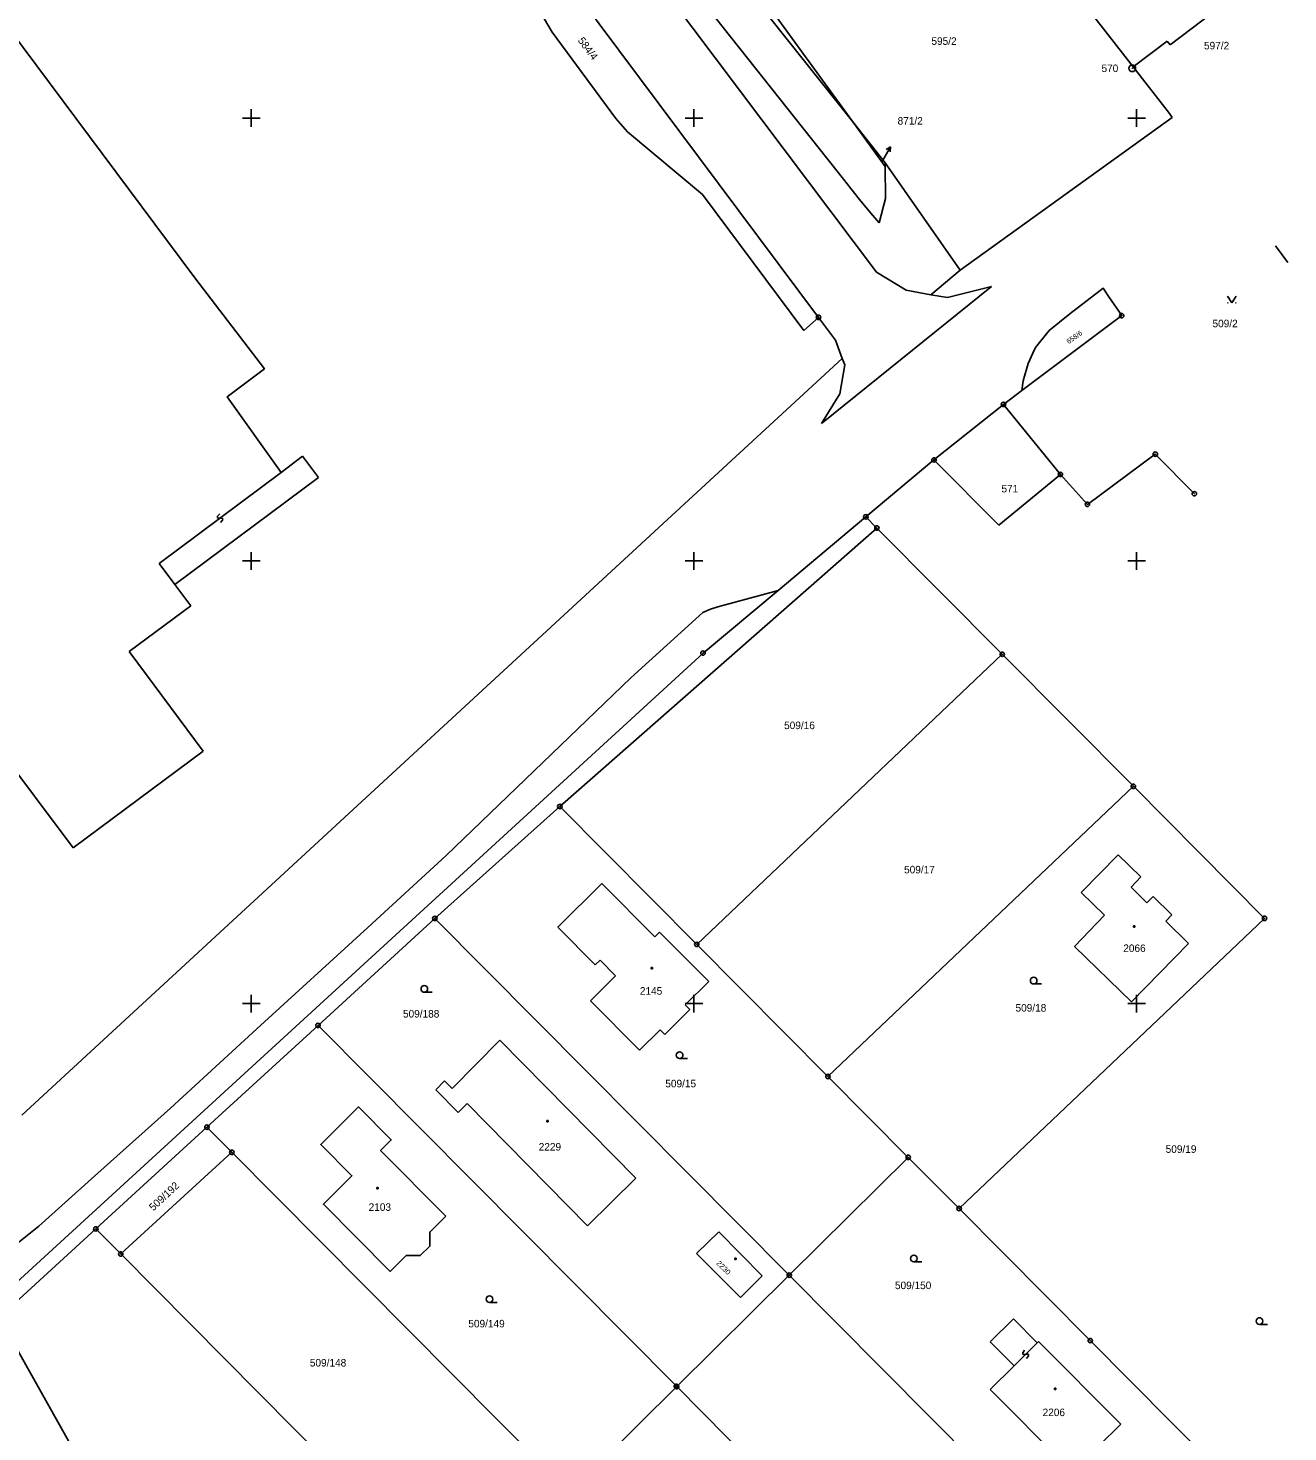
# Model space of a CAD drawing. Extents: x -493648 to -493033, y -1127718 to -1127026.
# Drawn here: x -493175.2 to -493032.9, y -1127598.4 to -1127439.8 of the extents above; entities that cross this region are included whole.
import ezdxf

# ---------------------------------------------------------------- set-up
doc = ezdxf.new("R2010")
doc.units = 0
doc.layers.add('katastrální mapa', color=7, linetype='Continuous')
doc.layers.add('síť', color=7, linetype='Continuous')

msp = doc.modelspace()

# ---------------------------------------------------------------- linework, layer by layer
at = {"layer": 'katastrální mapa'}
for p, q in [((-493126.36, -1127404.86), (-493079.37, -1127467.4)), ((-493118.62, -1127412.12), (-493083.09, -1127456.9)), ((-493182.89, -1127432.48), (-493156.39, -1127468.02)), ((-493095.08, -1127434.01), (-493082.05, -1127450.44)), ((-493094.36, -1127433.46), (-493082.05, -1127450.44)), ((-493057.26, -1127435.36), (-493050.37, -1127444.23)), ((-493046.21, -1127441.73), (-493041.37, -1127438.06)), ((-493050.37, -1127444.23), (-493046.53, -1127441.32)), ((-493046.53, -1127441.32), (-493046.21, -1127441.73)), ((-493050.37, -1127444.23), (-493046.26, -1127449.5)), ((-493069.91, -1127467.18), (-493045.96, -1127449.92)), ((-493046.26, -1127449.5), (-493045.96, -1127449.92)), ((-493082.05, -1127450.44), (-493078.4, -1127455.48)), ((-493082.05, -1127450.44), (-493078.4, -1127455.04)), ((-493078.56, -1127454.55), (-493077.81, -1127453.25)), ((-493077.81, -1127453.25), (-493078.27, -1127453.56)), ((-493077.81, -1127453.25), (-493077.84, -1127453.81)), ((-493078.75, -1127454.88), (-493078.56, -1127454.55)), ((-493078.4, -1127455.04), (-493069.91, -1127467.18)), ((-493078.4, -1127455.48), (-493078.4, -1127455.04)), ((-493078.4, -1127455.48), (-493078.36, -1127459.07)), ((-493083.09, -1127456.9), (-493082.29, -1127457.96)), ((-493082.29, -1127457.96), (-493081.3, -1127459.18)), ((-493081.3, -1127459.18), (-493080.03, -1127460.73)), ((-493079.06, -1127461.82), (-493078.36, -1127459.07)), ((-493080.03, -1127460.73), (-493079.06, -1127461.82)), ((-493034.31, -1127464.44), (-493032.9, -1127466.29)), ((-493079.37, -1127467.4), (-493076.02, -1127469.45)), ((-493073.23, -1127469.94), (-493069.91, -1127467.18)), ((-493085.58, -1127484.49), (-493066.4, -1127469)), ((-493071.37, -1127470.26), (-493066.4, -1127469)), ((-493076.02, -1127469.45), (-493073.23, -1127469.94)), ((-493073.23, -1127469.94), (-493071.37, -1127470.26)), ((-493051.67, -1127472.31), (-493053.12, -1127470.17)), ((-493039.74, -1127470.11), (-493039.24, -1127470.86)), ((-493039.24, -1127470.86), (-493038.74, -1127470.11)), ((-493062.96, -1127480.78), (-493051.67, -1127472.31)), ((-493039.74, -1127470.86), (-493039.64, -1127470.86)), ((-493038.84, -1127470.86), (-493038.74, -1127470.86)), ((-493102.04, -1127494.48), (-493083.24, -1127477.14)), ((-493083.52, -1127481.15), (-493082.96, -1127477.87)), ((-493083.24, -1127477.14), (-493082.96, -1127477.87)), ((-493085.58, -1127484.49), (-493083.52, -1127481.15)), ((-493065.03, -1127482.33), (-493062.96, -1127480.78)), ((-493072.88, -1127488.6), (-493065.03, -1127482.33)), ((-493065.03, -1127482.33), (-493058.6, -1127490.24)), ((-493146.63, -1127490.04), (-493144.22, -1127488.18)), ((-493144.22, -1127488.18), (-493142.4, -1127490.58)), ((-493055.55, -1127493.62), (-493047.88, -1127487.95)), ((-493047.88, -1127487.95), (-493043.47, -1127492.42)), ((-493080.58, -1127495.03), (-493072.88, -1127488.6)), ((-493072.88, -1127488.6), (-493065.56, -1127495.97)), ((-493160.41, -1127500.31), (-493146.63, -1127490.04)), ((-493142.4, -1127490.58), (-493158.64, -1127502.68)), ((-493065.56, -1127495.97), (-493058.6, -1127490.24)), ((-493058.6, -1127490.24), (-493055.55, -1127493.62)), ((-493175.91, -1127562.6), (-493102.04, -1127494.48)), ((-493153.81, -1127494.95), (-493153.83, -1127495.09)), ((-493153.83, -1127495.09), (-493153.77, -1127495.17)), ((-493153.56, -1127494.7), (-493153.81, -1127494.95)), ((-493153.77, -1127495.17), (-493153.63, -1127495.19)), ((-493153.63, -1127495.19), (-493153.41, -1127495.16)), ((-493153.23, -1127495.4), (-493153.48, -1127495.65)), ((-493153.41, -1127495.16), (-493153.27, -1127495.18)), ((-493153.27, -1127495.18), (-493153.21, -1127495.26)), ((-493153.21, -1127495.26), (-493153.23, -1127495.4)), ((-493080.58, -1127495.03), (-493090.5, -1127503.33)), ((-493079.33, -1127496.29), (-493080.58, -1127495.03)), ((-493115.14, -1127527.74), (-493079.33, -1127496.29)), ((-493079.33, -1127496.29), (-493065.17, -1127510.55)), ((-493158.64, -1127502.68), (-493160.41, -1127500.31)), ((-493158.64, -1127502.68), (-493156.84, -1127505.09)), ((-493098.97, -1127510.41), (-493090.5, -1127503.33)), ((-493090.5, -1127503.33), (-493097.31, -1127505.21)), ((-493156.84, -1127505.09), (-493163.78, -1127510.25)), ((-493163.78, -1127510.25), (-493155.42, -1127521.48)), ((-493177.87, -1127582.75), (-493098.97, -1127510.41)), ((-493099.68, -1127543.31), (-493065.17, -1127510.55)), ((-493065.17, -1127510.55), (-493050.36, -1127525.46)), ((-493170.1, -1127532.41), (-493179.09, -1127520.45)), ((-493155.42, -1127521.48), (-493170.1, -1127532.41)), ((-493084.86, -1127558.23), (-493050.36, -1127525.46)), ((-493050.36, -1127525.46), (-493035.54, -1127540.37)), ((-493129.26, -1127540.38), (-493115.14, -1127527.74)), ((-493115.14, -1127527.74), (-493099.68, -1127543.31)), ((-493052.09, -1127533.2), (-493056.24, -1127537.44)), ((-493049.52, -1127535.7), (-493052.09, -1127533.2)), ((-493050.61, -1127536.85), (-493049.52, -1127535.7)), ((-493115.36, -1127541.35), (-493110.39, -1127536.42)), ((-493110.39, -1127536.42), (-493104.41, -1127542.45)), ((-493048.82, -1127538.62), (-493050.61, -1127536.85)), ((-493056.24, -1127537.44), (-493053.62, -1127540)), ((-493048.12, -1127537.9), (-493048.82, -1127538.62)), ((-493046, -1127539.97), (-493048.12, -1127537.9)), ((-493142.46, -1127552.46), (-493129.26, -1127540.38)), ((-493129.26, -1127540.38), (-493089.23, -1127580.66)), ((-493070.04, -1127573.14), (-493035.54, -1127540.37)), ((-493053.62, -1127540), (-493057, -1127543.54)), ((-493046.7, -1127540.68), (-493046, -1127539.97)), ((-493111.14, -1127545.61), (-493115.36, -1127541.35)), ((-493104.41, -1127542.45), (-493103.88, -1127541.92)), ((-493103.88, -1127541.92), (-493098.32, -1127547.51)), ((-493050.36, -1127541.23), (-493050.21, -1127541.23)), ((-493050.36, -1127541.38), (-493050.36, -1127541.23)), ((-493050.21, -1127541.38), (-493050.36, -1127541.38)), ((-493050.21, -1127541.23), (-493050.21, -1127541.38)), ((-493044.12, -1127543.2), (-493046.7, -1127540.68)), ((-493099.68, -1127543.31), (-493084.86, -1127558.23)), ((-493057, -1127543.54), (-493050.56, -1127549.8)), ((-493050.56, -1127549.8), (-493044.12, -1127543.2)), ((-493110.6, -1127545.08), (-493111.14, -1127545.61)), ((-493108.84, -1127546.85), (-493110.6, -1127545.08)), ((-493104.84, -1127545.91), (-493104.69, -1127545.91)), ((-493104.84, -1127546.06), (-493104.84, -1127545.91)), ((-493104.69, -1127546.06), (-493104.84, -1127546.06)), ((-493104.69, -1127545.91), (-493104.69, -1127546.06)), ((-493111.68, -1127549.67), (-493108.84, -1127546.85)), ((-493098.32, -1127547.51), (-493100.98, -1127550.15)), ((-493061.62, -1127547.78), (-493060.74, -1127547.78)), ((-493130.45, -1127548.72), (-493129.57, -1127548.72)), ((-493106.13, -1127555.26), (-493111.68, -1127549.67)), ((-493100.46, -1127550.68), (-493103.29, -1127553.5)), ((-493100.98, -1127550.15), (-493100.46, -1127550.68)), ((-493155.01, -1127563.95), (-493142.46, -1127552.46)), ((-493142.46, -1127552.46), (-493101.94, -1127593.25)), ((-493103.82, -1127552.97), (-493106.13, -1127555.26)), ((-493103.29, -1127553.5), (-493103.82, -1127552.97)), ((-493127.3, -1127559.59), (-493121.92, -1127554.12)), ((-493121.92, -1127554.12), (-493106.56, -1127569.72)), ((-493101.61, -1127556.2), (-493100.73, -1127556.2)), ((-493129.15, -1127559.75), (-493128.16, -1127558.72)), ((-493128.16, -1127558.72), (-493127.3, -1127559.59)), ((-493084.86, -1127558.23), (-493075.79, -1127567.36)), ((-493126.63, -1127562.29), (-493129.15, -1127559.75)), ((-493125.62, -1127561.28), (-493126.63, -1127562.29)), ((-493112.01, -1127575.08), (-493125.62, -1127561.28)), ((-493167.56, -1127575.44), (-493155.01, -1127563.95)), ((-493155.01, -1127563.95), (-493152.19, -1127566.79)), ((-493116.62, -1127563.19), (-493116.47, -1127563.19)), ((-493116.62, -1127563.34), (-493116.62, -1127563.19)), ((-493116.47, -1127563.34), (-493116.62, -1127563.34)), ((-493116.47, -1127563.19), (-493116.47, -1127563.34)), ((-493164.74, -1127578.27), (-493152.19, -1127566.79)), ((-493152.19, -1127566.79), (-493114.02, -1127605.21)), ((-493089.23, -1127580.66), (-493075.79, -1127567.36)), ((-493075.79, -1127567.36), (-493070.04, -1127573.14)), ((-493106.56, -1127569.72), (-493112.01, -1127575.08)), ((-493135.8, -1127570.76), (-493135.65, -1127570.76)), ((-493135.8, -1127570.91), (-493135.8, -1127570.76)), ((-493135.65, -1127570.91), (-493135.8, -1127570.91)), ((-493135.65, -1127570.76), (-493135.65, -1127570.91)), ((-493070.04, -1127573.14), (-493055.23, -1127588.05)), ((-493176.68, -1127583.78), (-493167.56, -1127575.44)), ((-493167.56, -1127575.44), (-493164.74, -1127578.27)), ((-493099.72, -1127578.22), (-493097.19, -1127575.77)), ((-493097.19, -1127575.77), (-493092.27, -1127580.74)), ((-493164.74, -1127578.27), (-493126.1, -1127617.17)), ((-493094.75, -1127583.2), (-493099.72, -1127578.22)), ((-493095.39, -1127578.76), (-493095.24, -1127578.76)), ((-493095.39, -1127578.91), (-493095.39, -1127578.76)), ((-493095.24, -1127578.91), (-493095.39, -1127578.91)), ((-493095.24, -1127578.76), (-493095.24, -1127578.91)), ((-493075.15, -1127579.15), (-493074.27, -1127579.15)), ((-493089.23, -1127580.66), (-493101.94, -1127593.25)), ((-493092.27, -1127580.74), (-493094.75, -1127583.2)), ((-493089.23, -1127580.66), (-493050.24, -1127619.91)), ((-493123.1, -1127583.74), (-493122.22, -1127583.74)), ((-493178.63, -1127585.2), (-493150.81, -1127634.64)), ((-493066.53, -1127588.21), (-493063.91, -1127585.6)), ((-493063.91, -1127585.6), (-493061.23, -1127588.3)), ((-493036.1, -1127586.22), (-493035.22, -1127586.22)), ((-493055.23, -1127588.05), (-493036.53, -1127606.88)), ((-493063.84, -1127590.91), (-493066.53, -1127588.21)), ((-493063.84, -1127590.91), (-493061.23, -1127588.3)), ((-493062.64, -1127589.15), (-493062.85, -1127589.43)), ((-493062.85, -1127589.43), (-493062.85, -1127589.57)), ((-493062.85, -1127589.57), (-493062.78, -1127589.64)), ((-493062.78, -1127589.64), (-493062.64, -1127589.64)), ((-493062.64, -1127589.64), (-493062.43, -1127589.57)), ((-493062.43, -1127589.57), (-493062.29, -1127589.57)), ((-493062.29, -1127589.57), (-493062.22, -1127589.64)), ((-493062.22, -1127589.64), (-493062.22, -1127589.78)), ((-493061.23, -1127588.3), (-493061.09, -1127588.16)), ((-493061.09, -1127588.16), (-493051.78, -1127597.5)), ((-493066.52, -1127593.59), (-493063.84, -1127590.91)), ((-493062.22, -1127589.78), (-493062.43, -1127590.06)), ((-493114.02, -1127605.21), (-493101.94, -1127593.25)), ((-493101.94, -1127593.25), (-493063.22, -1127632.23)), ((-493057.22, -1127602.91), (-493066.52, -1127593.59)), ((-493059.26, -1127593.41), (-493059.11, -1127593.41)), ((-493059.26, -1127593.56), (-493059.26, -1127593.41)), ((-493059.11, -1127593.56), (-493059.26, -1127593.56)), ((-493059.11, -1127593.41), (-493059.11, -1127593.56)), ((-493051.78, -1127597.5), (-493054.29, -1127599.99))]:
    msp.add_line(p, q, dxfattribs=at)
for points in [[(-493085.93, -1127472.5), (-493135.46, -1127406.14), (-493166.74, -1127364.1)], [(-493085.93, -1127472.5), (-493087.58, -1127473.97), (-493099.04, -1127458.64), (-493107.51, -1127451.54), (-493108.83, -1127450.05), (-493116, -1127440.29), (-493118.72, -1127435.67), (-493126.88, -1127421.87), (-493146.06, -1127398.58), (-493147.9, -1127396.18), (-493164.64, -1127374.21), (-493166.11, -1127372.81), (-493167.7, -1127371.62), (-493168.62, -1127371.17), (-493170.51, -1127370.59), (-493172.5, -1127370.44), (-493174.51, -1127370.65)], [(-493156.39, -1127468.02), (-493148.51, -1127478.3), (-493152.72, -1127481.48), (-493146.63, -1127490.04)], [(-493053.12, -1127470.17), (-493053.76, -1127469.22), (-493057.53, -1127472.12), (-493059.88, -1127474), (-493061.4, -1127475.89), (-493061.7, -1127476.54)], [(-493083.24, -1127477.14), (-493084.01, -1127475.08), (-493085.93, -1127472.5)], [(-493061.7, -1127476.54), (-493062.24, -1127477.71), (-493062.82, -1127479.67), (-493062.96, -1127480.78)], [(-493097.31, -1127505.21), (-493098.12, -1127505.44), (-493098.98, -1127505.84), (-493107.13, -1127513.2), (-493127.98, -1127533.26), (-493136.84, -1127541.39), (-493149.38, -1127552.86), (-493159.12, -1127561.82), (-493168.03, -1127569.78), (-493174.01, -1127575.14), (-493177.93, -1127578.28), (-493182.72, -1127581.82), (-493186.93, -1127584.59), (-493191.56, -1127587.36), (-493199.02, -1127591.33), (-493200.84, -1127592.19), (-493208.3, -1127595.08), (-493221.5, -1127599.86), (-493230.41, -1127602.91), (-493259.01, -1127611.75), (-493280.04, -1127618.2), (-493281.66, -1127619.38), (-493281.8, -1127619.61)], [(-493128.03, -1127574), (-493135.4, -1127566.59), (-493134.19, -1127565.39), (-493137.89, -1127561.66), (-493142.15, -1127565.89), (-493138.62, -1127569.44), (-493141.85, -1127572.65), (-493134.31, -1127580.24), (-493132.51, -1127578.45), (-493130.91, -1127578.46), (-493129.83, -1127577.39), (-493129.83, -1127575.79), (-493128.03, -1127574)]]:
    msp.add_lwpolyline(points, dxfattribs=at)
for centre, radius in [((-493050.48, -1127444.38), 0.375), ((-493050.48, -1127444.38), 0.005), ((-493085.93, -1127472.5), 0.25), ((-493051.67, -1127472.31), 0.25), ((-493051.67, -1127472.31), 0.005), ((-493085.93, -1127472.5), 0.005), ((-493065.03, -1127482.33), 0.25), ((-493065.03, -1127482.33), 0.005), ((-493047.88, -1127487.95), 0.25), ((-493047.88, -1127487.95), 0.005), ((-493072.88, -1127488.6), 0.25), ((-493072.88, -1127488.6), 0.005), ((-493058.6, -1127490.24), 0.25), ((-493058.6, -1127490.24), 0.005), ((-493043.47, -1127492.42), 0.25), ((-493043.47, -1127492.42), 0.005), ((-493055.55, -1127493.62), 0.25), ((-493055.55, -1127493.62), 0.005), ((-493080.58, -1127495.03), 0.25), ((-493080.58, -1127495.03), 0.005), ((-493079.33, -1127496.29), 0.25), ((-493079.33, -1127496.29), 0.005), ((-493098.97, -1127510.41), 0.25), ((-493065.17, -1127510.55), 0.25), ((-493098.97, -1127510.41), 0.005), ((-493065.17, -1127510.55), 0.005), ((-493050.36, -1127525.46), 0.25), ((-493050.36, -1127525.46), 0.005), ((-493115.14, -1127527.74), 0.25), ((-493115.14, -1127527.74), 0.005), ((-493129.26, -1127540.38), 0.25), ((-493129.26, -1127540.38), 0.005), ((-493035.54, -1127540.37), 0.25), ((-493035.54, -1127540.37), 0.005), ((-493099.68, -1127543.31), 0.25), ((-493099.68, -1127543.31), 0.005), ((-493130.45, -1127548.345), 0.375), ((-493061.62, -1127547.405), 0.375), ((-493142.46, -1127552.46), 0.25), ((-493142.46, -1127552.46), 0.005), ((-493101.61, -1127555.825), 0.375), ((-493084.86, -1127558.23), 0.25), ((-493084.86, -1127558.23), 0.005), ((-493155.01, -1127563.95), 0.25), ((-493155.01, -1127563.95), 0.005), ((-493152.19, -1127566.79), 0.25), ((-493152.19, -1127566.79), 0.005), ((-493075.79, -1127567.36), 0.25), ((-493075.79, -1127567.36), 0.005), ((-493070.04, -1127573.14), 0.25), ((-493070.04, -1127573.14), 0.005), ((-493167.56, -1127575.44), 0.25), ((-493167.56, -1127575.44), 0.005), ((-493164.74, -1127578.27), 0.25), ((-493164.74, -1127578.27), 0.005), ((-493075.15, -1127578.775), 0.375), ((-493089.23, -1127580.66), 0.25), ((-493089.23, -1127580.66), 0.005), ((-493123.1, -1127583.365), 0.375), ((-493036.1, -1127585.845), 0.375), ((-493055.23, -1127588.05), 0.25), ((-493055.23, -1127588.05), 0.005), ((-493101.98, -1127593.21), 0.25), ((-493101.94, -1127593.25), 0.25), ((-493101.98, -1127593.21), 0.005), ((-493101.94, -1127593.25), 0.005)]:
    msp.add_circle(centre, radius, dxfattribs=at)
at = {"layer": 'síť'}
for p, q in [((-493151, -1127450), (-493149, -1127450)), ((-493150, -1127449), (-493150, -1127451)), ((-493101, -1127450), (-493099, -1127450)), ((-493100, -1127449), (-493100, -1127451)), ((-493051, -1127450), (-493049, -1127450)), ((-493050, -1127449), (-493050, -1127451)), ((-493150, -1127499), (-493150, -1127501)), ((-493100, -1127499), (-493100, -1127501)), ((-493050, -1127499), (-493050, -1127501)), ((-493151, -1127500), (-493149, -1127500)), ((-493101, -1127500), (-493099, -1127500)), ((-493051, -1127500), (-493049, -1127500)), ((-493151, -1127550), (-493149, -1127550)), ((-493150, -1127549), (-493150, -1127551)), ((-493101, -1127550), (-493099, -1127550)), ((-493100, -1127549), (-493100, -1127551)), ((-493051, -1127550), (-493049, -1127550)), ((-493050, -1127549), (-493050, -1127551))]:
    msp.add_line(p, q, dxfattribs=at)

# ---------------------------------------------------------------- texts
at = {"layer": 'katastrální mapa'}
for s, height, rotation, p in [('584/4', 0.849996, 307.0933194, (-493113.16, -1127441.26)), ('871/2', 0.049998, 311.8202083, (-493078.78, -1127454.9)), ('658/6', 0.569994, 35.2277083, (-493057.67, -1127475.54)), ('509/192', 0.849996, 43.1999972, (-493161.06, -1127573.47)), ('2230', 0.599994, 314.9999972, (-493097.51, -1127579.38))]:
    msp.add_text(s, height=height, rotation=rotation, dxfattribs=at).set_placement(p)
for s, p in [('595/2', (-493073.17, -1127441.73)), ('597/2', (-493042.38, -1127442.24)), ('570', (-493053.96, -1127444.8)), ('871/2', (-493076.99, -1127450.74)), ('509/2', (-493041.42, -1127473.62)), ('571', (-493065.26, -1127492.27)), ('509/16', (-493089.81, -1127519)), ('509/17', (-493076.26, -1127535.29)), ('2066', (-493051.5, -1127544.17)), ('2145', (-493106.1, -1127548.99)), ('509/18', (-493063.67, -1127550.9)), ('509/188', (-493132.86, -1127551.57)), ('509/15', (-493103.23, -1127559.45)), ('2229', (-493117.53, -1127566.59)), ('509/19', (-493046.71, -1127566.85)), ('2103', (-493136.74, -1127573.4)), ('509/150', (-493077.29, -1127582.24)), ('509/149', (-493125.48, -1127586.56)), ('509/148', (-493143.38, -1127590.98)), ('2206', (-493060.61, -1127596.58))]:
    msp.add_text(s, height=0.849996, dxfattribs=at).set_placement(p)

doc.saveas('drawing.dxf')
